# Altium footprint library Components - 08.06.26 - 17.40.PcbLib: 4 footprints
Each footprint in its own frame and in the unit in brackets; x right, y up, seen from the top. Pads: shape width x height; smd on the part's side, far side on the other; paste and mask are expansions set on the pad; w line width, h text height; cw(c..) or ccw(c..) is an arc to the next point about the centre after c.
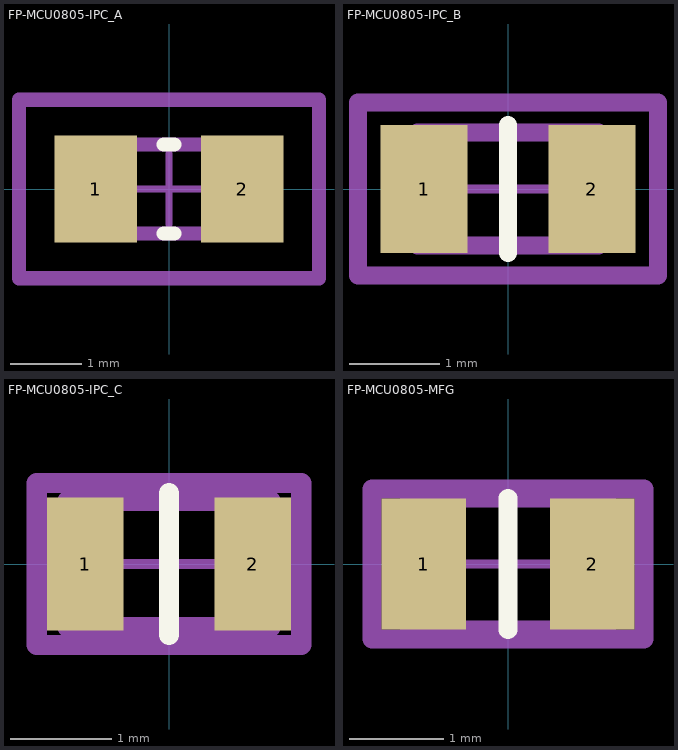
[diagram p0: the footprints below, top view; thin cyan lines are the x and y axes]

## FP-MCU0805-IPC_A [mm]
pads (2):
  rect 1.159x1.508 smd paste+0 mask+0: 1(-1.027,0) 2(1.027,0)
Top Overlay:
  lines w0.2: -0.072,-0.625 0.072,-0.625 ; -0.072,0.625 0.072,0.625
Top Assembly:
  lines w0.2: -2.106,-1.254 2.106,-1.254 2.106,1.254 -2.106,1.254 -2.106,-1.254
  text ".Designator" at 0,0.188 h1
Top 3D Body:
  lines w0.2: -1,-0.625 1,-0.625 1,0.625 -1,0.625 -1,-0.625
Top Courtyard:
  lines w0.2: -2.106,-1.254 2.106,-1.254 2.106,1.254 -2.106,1.254 -2.106,-1.254
Top Component Center:
  lines w0.1: -0.5,0 0.5,0 ; 0,-0.5 0,0.5
3D body "Res_Vishay_MCU08050D2210BP100_eec.STEP": height 0.25, standoff 0, extent -2.106,-1.254 2.106,1.254

## FP-MCU0805-IPC_B [mm]
pads (2):
  rect 0.959x1.408 smd paste+0 mask+0: 1(-0.927,0) 2(0.927,0)
Top Overlay:
  lines w0.2: 0,-0.704 0,0.704
Top Assembly:
  lines w0.2: -1.656,-0.954 1.656,-0.954 1.656,0.954 -1.656,0.954 -1.656,-0.954
  text ".Designator" at 0,-0.001 h1
Top 3D Body:
  lines w0.2: -1,-0.625 1,-0.625 1,0.625 -1,0.625 -1,-0.625
Top Courtyard:
  lines w0.2: -1.656,-0.954 1.656,-0.954 1.656,0.954 -1.656,0.954 -1.656,-0.954
Top Component Center:
  lines w0.1: -0.5,0 0.5,0 ; 0,-0.5 0,0.5
3D body "Res_Vishay_MCU08050D2210BP100_eec.STEP": height 0.25, standoff 0, extent -1.656,-0.954 1.656,0.954

## FP-MCU0805-IPC_C [mm]
pads (2):
  rect 0.759x1.308 smd paste+0 mask+0: 1(-0.827,0) 2(0.827,0)
Top Overlay:
  lines w0.2: 0,-0.7 0,0.7
Top Assembly:
  lines w0.2: -1.306,-0.8 1.306,-0.8 1.306,0.8 -1.306,0.8 -1.306,-0.8
  text ".Designator" at 0,-0.001 h1
Top 3D Body:
  lines w0.2: -1,-0.625 1,-0.625 1,0.625 -1,0.625 -1,-0.625
Top Courtyard:
  lines w0.2: -1.306,-0.8 1.306,-0.8 1.306,0.8 -1.306,0.8 -1.306,-0.8
Top Component Center:
  lines w0.1: -0.5,0 0.5,0 ; 0,-0.5 0,0.5
3D body "Res_Vishay_MCU08050D2210BP100_eec.STEP": height 0.25, standoff 0, extent -1.306,-0.8 1.306,0.8

## FP-MCU0805-MFG [mm]
pads (2):
  rect 0.9x1.4 smd paste+0 mask+0: 1(-0.9,0) 2(0.9,0)
Top Overlay:
  lines w0.2: 0,-0.7 0,0.7
Top Assembly:
  lines w0.2: -1.45,-0.8 1.45,-0.8 1.45,0.8 -1.45,0.8 -1.45,-0.8
  text ".Designator" at 0,-0.001 h1
Top 3D Body:
  lines w0.2: -1.05,-0.7 1.05,-0.7 1.05,0.7 -1.05,0.7 -1.05,-0.7
Top Courtyard:
  lines w0.2: -1.45,-0.8 1.45,-0.8 1.45,0.8 -1.45,0.8 -1.45,-0.8
Top Component Center:
  lines w0.1: -0.5,0 0.5,0 ; 0,-0.5 0,0.5
3D body "Res_Vishay_MCU08050D2210BP100_eec.STEP": height 0.25, standoff 0, extent -1.45,-0.8 1.45,0.8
